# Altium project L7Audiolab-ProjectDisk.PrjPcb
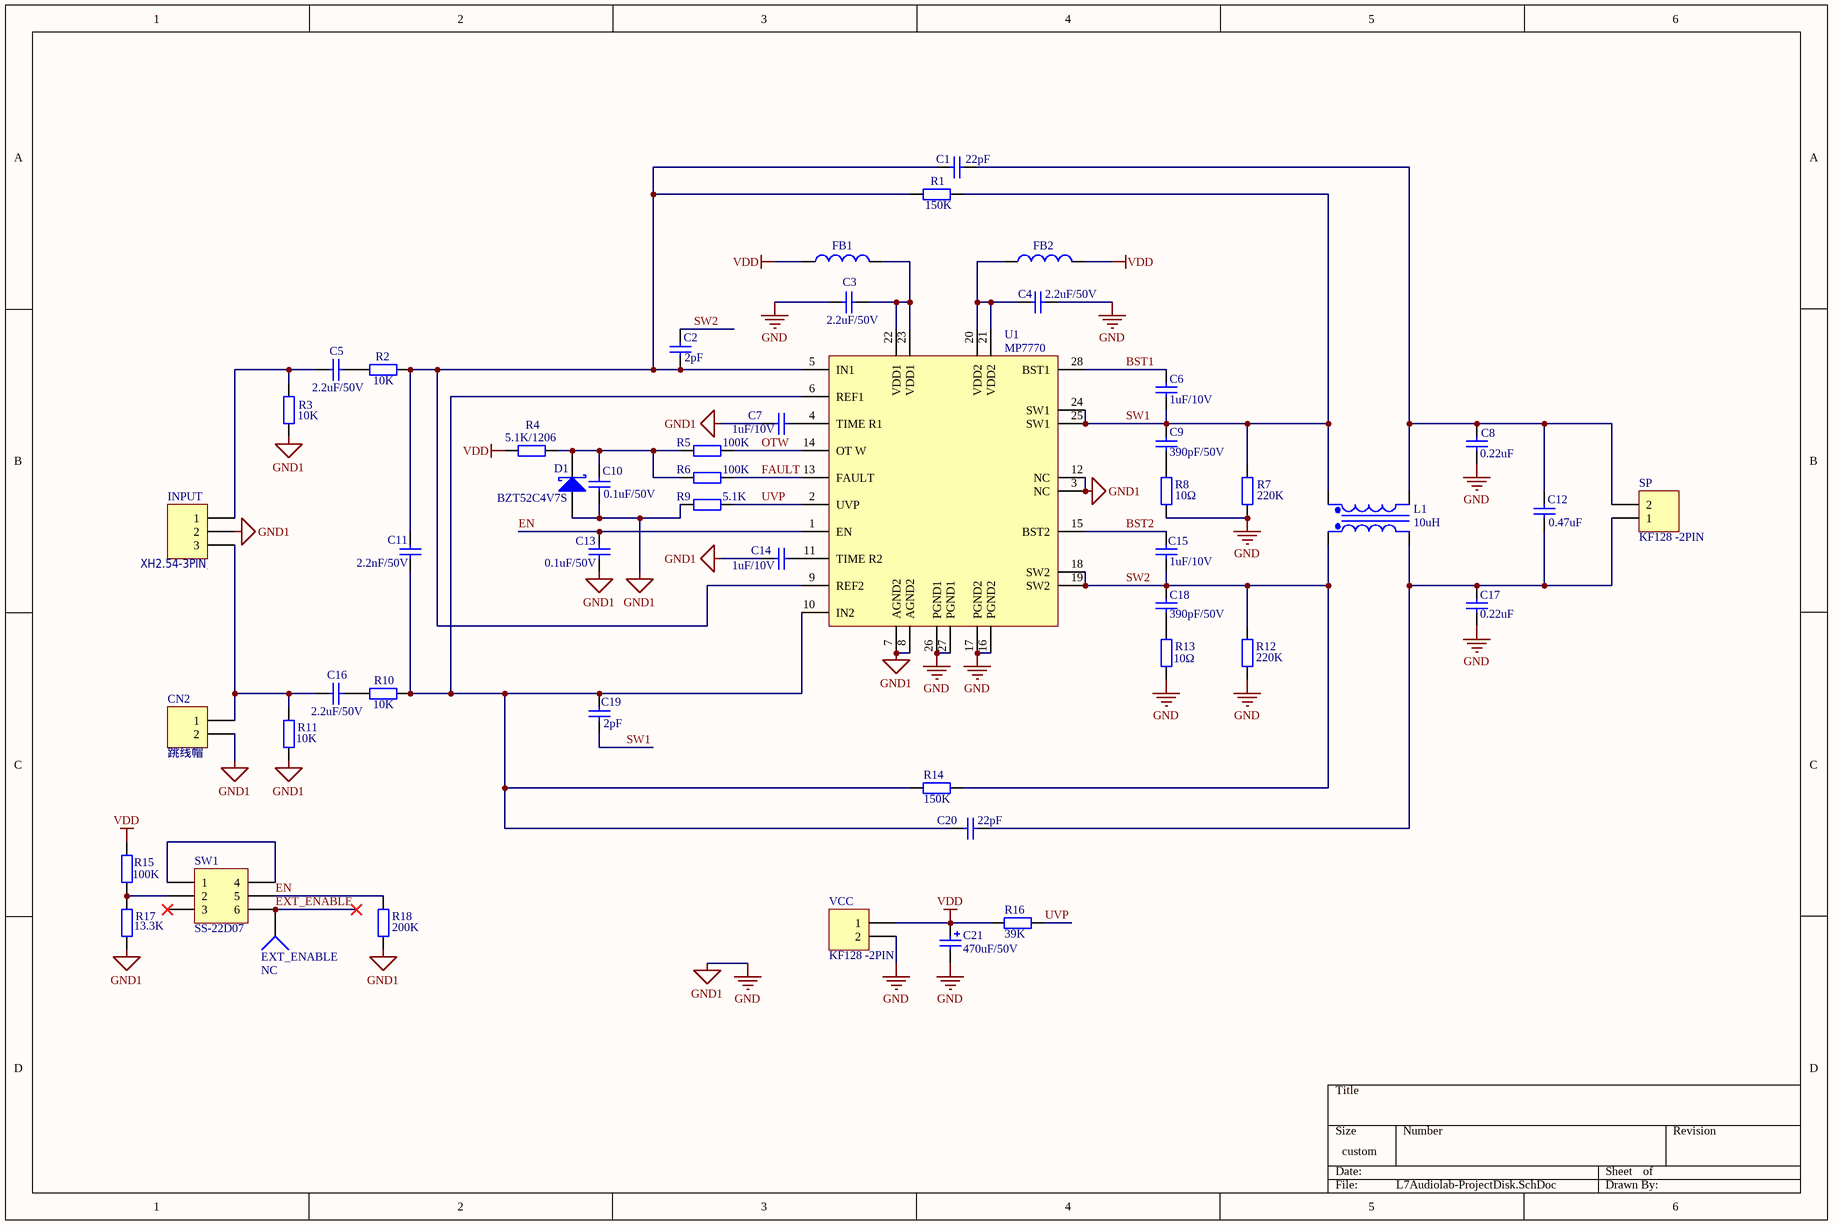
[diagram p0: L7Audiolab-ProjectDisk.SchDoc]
1 sheet, 50 parts. Net scope: global (net labels, ports and power ports of the same name join across sheets).
Board file: L7Audiolab-ProjectDisk.PcbDoc

## Sheet L7Audiolab-ProjectDisk.SchDoc
size 342 x 228 mm; PageSetup: Record=PageOptions|CenterHorizontal=True|CenterVertical=True|PrintScale=3.42|XCorrection=1.00|YCorrection=1.00|PrintKind=0|BorderSize=5000000|LeftOffset=0|BottomOffset=0|Orientation=2|PaperLength=1000|PaperWidth=1000|Scale=100|PaperSource=7|PrintQuality=-4|MediaType=1|DitherType=10|PaperKind=A0|PrintScaleMode=1

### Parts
C1  22pF  [0805_C]
C2  2pF  [0805_C]
C3  2.2uF/50V  [1206-C]
C4  2.2uF/50V  [1206-C]
C5  2.2uF/50V  [1206_C]
C6  1uF/10V  [0805_C]
C7  1uF/10V  [0805_C]
C8  0.22uF  [独石电容5.08MM]
C9  390pF/50V  [0805_C]
C10  0.1uF/50V  [0805_C]
C11  2.2nF/50V  [0805_C]
C12  0.47uF  [独石电容5.08MM]
C13  0.1uF/50V  [0805_C]
C14  1uF/10V  [0805_C]
C15  1uF/10V  [0805_C]
C16  2.2uF/50V  [1206_C]
C17  0.22uF  [独石电容5.08MM]
C18  390pF/50V  [0805_C]
C19  2pF  [0805_C]
C20  22pF  [0805_C]
C21  470uF/50V  [10*17]
CN2  跳线帽  [HDR1X2]
D1  BZT52C4V7S  [LC-SOD-323]
EXT_ENABLE  NC  [PIN1]
FB1  (no value)  [1206-R]
FB2  (no value)  [1206-R]
INPUT  XH2.54-3PINֱ  [XH2.54-3PINֱ]
L1  10uH  [7W14A-100M功放电感]
R1  150K  [0805_R]
R2  10K  [0805_R]
R3  10K  [0805_R]
R4  5.1K/1206  [1206-R]
R5  100K  [0805_R]
R6  100K  [0805_R]
R7  220K  [0805_R]
R8  10Ω  [0805_R]
R9  5.1K  [0805_R]
R10  10K  [0805_R]
R11  10K  [0805_R]
R12  220K  [0805_R]
R13  10Ω  [0805_R]
R14  150K  [0805_R]
R15  100K  [1206-R]
R16  39K  [0805_R]
R17  13.3K  [1206-R]
R18  200K  [1206-R]
SP  KF128 -2PIN  [KF128 -2PIN]
SW1  SS-22D07  [SS-22D07]
U1  MP7770  [LC-TSSOP-28]
VCC  KF128 -2PIN  [KF128 -2PIN]

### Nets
GND: C3.1 C4.1 C7.2 C8.1 C10.2 C13.2 C14.2 C17.1 C21.2 CN2.2 D1.1(A) INPUT.2 R3.2 R7.1 R8.1 R9.2 R11.2 R12.1 R13.1 R17.2 R18.2 U1.3(NC) U1.7(AGND2) U1.8(AGND2) U1.12(NC) U1.16(PGND2) U1.17(PGND2) U1.26(PGND1) U1.27(PGND1) VCC.2  [also labelled GND1]
VDD: C21.1 FB1.2 FB2.2 R4.2 R15.1 R16.1 VCC.1
BST1: C6.2 U1.28(BST1)
BST2: C15.2 U1.15(BST2)
EN: C13.1 R18.1 SW1.5 U1.1(EN)
EXT_ENABLE: EXT_ENABLE.1 SW1.6
FAULT: R6.1 U1.13(FAULT)
OTW: R5.1 U1.14(OT_W)
SW1: C6.1 C9.2 C19.1 L1.1(Sec+) R1.1 R7.2 U1.24(SW1) U1.25(SW1)
SW2: C2.2 C15.1 C18.2 L1.3(Pri+) R12.2 R14.1 U1.18(SW2) U1.19(SW2)
UVP: R9.1 R16.2 U1.2(UVP)
NetC1_1: C1.1 C8.2 C12.2 L1.2(Sec-) SP.2
NetC1_2: C1.2 C2.1 C11.1 R1.2 R2.1 U1.5(IN1) U1.9(REF2)
NetC3_2: C3.2 FB1.1 U1.22(VDD1) U1.23(VDD1)
NetC4_2: C4.2 FB2.1 U1.20(VDD2) U1.21(VDD2)
NetC5_1: C5.1 INPUT.1 R3.1
NetC5_2: C5.2 R2.2
NetC7_1: C7.1 U1.4(TIME_R1)
NetC9_1: C9.1 R8.2
NetC10_1: C10.1 D1.2 R4.1 R5.2 R6.2
NetC11_2: C11.2 C19.2 C20.2 R10.1 R14.2 U1.6(REF1) U1.10(IN2)
NetC12_1: C12.1 C17.2 C20.1 L1.4(Pri-) SP.1
NetC14_1: C14.1 U1.11(TIME_R2)
NetC16_1: C16.1 CN2.1 INPUT.3 R11.1
NetC16_2: C16.2 R10.2
NetC18_1: C18.1 R13.2
NetR15_2: R15.2 R17.1 SW1.2
NetSW1_1: SW1.1 SW1.4

Not connected (* = marked no-connect by the designer): SW1 3*

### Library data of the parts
C1-C20 = Cap: Capacitor; Value: 100pF
C21 = Cap Pol2: Polarized Capacitor (Axial); Value: 100pF
CN2 SP VCC = Header 2: Header, 2-Pin
D1 = Diode BAT17: Silicon RF Schottky Diode for Mixer Applications in the VHF/UHF Range; Note: Pin 2 is not connected and not drawn.
EXT_ENABLE = Socket
FB1 FB2 = Inductor: Code_IEC: 1005; Value: 10mH
INPUT = Header 3: Header, 3-Pin
L1 = Trans Cupl: Transformer (Coupled Inductor Model)
R1-R18 = Res2: Resistor; Value: 1K
SW1 = Header 3X2: Header, 3-Pin, Dual row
